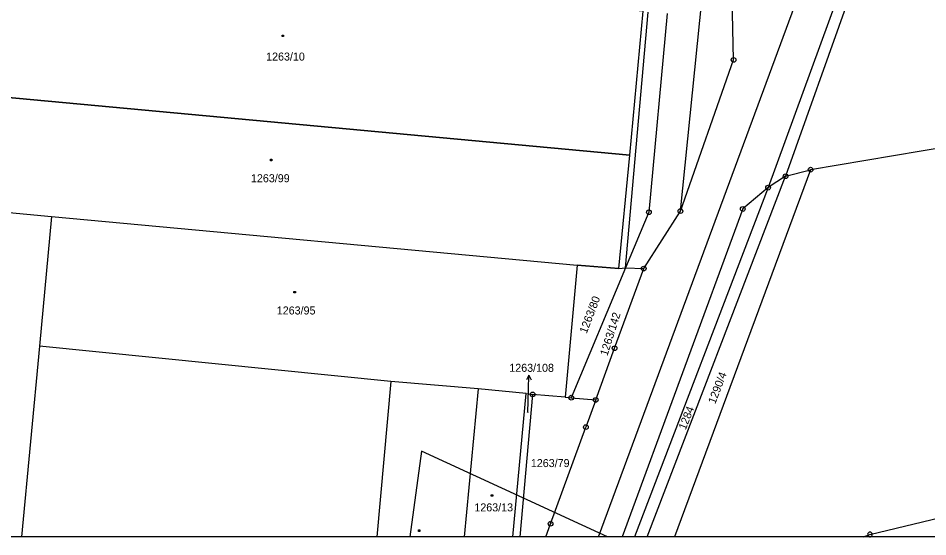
# Model space of a CAD drawing. Extents: x -468021 to -466942, y -1130484 to -1128584.
# Drawn here: x -467501 to -467307.8, y -1130484.4 to -1130374.3 of the extents above; entities that cross this region are included whole.
import ezdxf

# ---------------------------------------------------------------- set-up
doc = ezdxf.new("R2010")
doc.units = 0
for name, color, linetype in [('22-Odběrná místa-šrafy', 7, 'Continuous'), ('Default', 7, 'Continuous'), ('DKM', 7, 'Continuous')]:
    doc.layers.add(name, color=color, linetype=linetype)

msp = doc.modelspace()

# ---------------------------------------------------------------- linework, layer by layer
at = {"layer": '22-Odběrná místa-šrafy'}
for points in [[(-467504.57, -1130390.98), (-467371.12, -1130403.34), (-467368.24, -1130372.8), (-467371.68, -1130372.48), (-467375.66, -1130372.12), (-467378.16, -1130371.89)], [(-467371.12, -1130403.34), (-467504.57, -1130390.98), (-467506.83, -1130415.18), (-467504.4, -1130415.41), (-467493.89, -1130416.38), (-467382.28, -1130426.72), (-467373.43, -1130427.45), (-467371.12, -1130403.34)]]:
    msp.add_lwpolyline(points, dxfattribs=at)
at = {"layer": 'Default'}
msp.add_lwpolyline([(-468020.6, -1128583.91), (-466941.68, -1128583.91), (-466941.68, -1130484.41), (-468020.6, -1130484.41)], close=True, dxfattribs=at)
at = {"layer": 'DKM'}
for p, q in [((-467377.72, -1130484.41), (-467260.66, -1130167.54)), ((-467360.35, -1130415.25), (-467345.02, -1130264.42)), ((-467323.73, -1130360.85), (-467341.73, -1130410.26)), ((-467321.65, -1130361.71), (-467338.03, -1130407.84)), ((-467349.06, -1130383.13), (-467349.37, -1130369.9)), ((-467372, -1130427.28), (-467367.18, -1130372.96)), ((-467371.12, -1130403.34), (-467368.24, -1130372.8)), ((-467363.2, -1130373.31), (-467367.06, -1130415.49)), ((-467444.95, -1130377.87), (-467444.65, -1130377.87)), ((-467444.95, -1130378.17), (-467444.95, -1130377.87)), ((-467444.65, -1130378.17), (-467444.95, -1130378.17)), ((-467444.65, -1130377.87), (-467444.65, -1130378.17)), ((-467360.35, -1130415.25), (-467349.06, -1130383.13)), ((-467210.75, -1130386.12), (-467332.71, -1130406.44)), ((-467371.12, -1130403.34), (-467504.57, -1130390.98)), ((-467447.4, -1130404.23), (-467447.1, -1130404.23)), ((-467447.4, -1130404.53), (-467447.4, -1130404.23)), ((-467447.1, -1130404.23), (-467447.1, -1130404.53)), ((-467373.43, -1130427.45), (-467371.12, -1130403.34)), ((-467447.1, -1130404.53), (-467447.4, -1130404.53)), ((-467367.41, -1130484.41), (-467338.03, -1130407.84)), ((-467332.71, -1130406.44), (-467361.63, -1130484.41)), ((-467338.03, -1130407.84), (-467341.73, -1130410.26)), ((-467338.03, -1130407.84), (-467332.71, -1130406.44)), ((-467341.73, -1130410.26), (-467370.13, -1130484.41)), ((-467341.73, -1130410.26), (-467347.11, -1130414.79)), ((-467504.4, -1130415.41), (-467493.89, -1130416.38)), ((-467347.11, -1130414.79), (-467372.72, -1130484.41)), ((-467367.06, -1130415.49), (-467372, -1130427.28)), ((-467368.15, -1130427.44), (-467360.35, -1130415.25)), ((-467493.89, -1130416.38), (-467496.46, -1130443.91)), ((-467493.89, -1130416.38), (-467382.28, -1130426.72)), ((-467382.28, -1130426.72), (-467384.86, -1130454.74)), ((-467372, -1130427.28), (-467383.54, -1130454.86)), ((-467373.43, -1130427.45), (-467382.28, -1130426.72)), ((-467374.33, -1130444.36), (-467368.15, -1130427.44)), ((-467373.43, -1130427.45), (-467372, -1130427.28)), ((-467372, -1130427.28), (-467368.15, -1130427.44)), ((-467442.43, -1130432.32), (-467442.13, -1130432.32)), ((-467442.43, -1130432.62), (-467442.43, -1130432.32)), ((-467442.13, -1130432.62), (-467442.43, -1130432.62)), ((-467442.13, -1130432.32), (-467442.13, -1130432.62)), ((-467496.46, -1130443.91), (-467500.26, -1130484.41)), ((-467421.87, -1130451.44), (-467496.46, -1130443.91)), ((-467378.34, -1130455.35), (-467374.33, -1130444.36)), ((-467392.55, -1130450.06), (-467393.08, -1130451.05)), ((-467392.63, -1130453.06), (-467392.55, -1130450.06)), ((-467392.55, -1130450.06), (-467392.08, -1130451.07)), ((-467421.87, -1130451.44), (-467424.85, -1130484.41)), ((-467403.29, -1130453.01), (-467421.87, -1130451.44)), ((-467403.29, -1130453.01), (-467406.29, -1130484.41)), ((-467393.11, -1130453.97), (-467403.29, -1130453.01)), ((-467395.97, -1130484.41), (-467393.11, -1130453.97)), ((-467391.75, -1130454.16), (-467394.48, -1130484.41)), ((-467393.11, -1130453.97), (-467391.75, -1130454.16)), ((-467392.76, -1130457.98), (-467392.63, -1130453.06)), ((-467384.86, -1130454.74), (-467391.75, -1130454.16)), ((-467384.86, -1130454.74), (-467383.54, -1130454.86)), ((-467383.54, -1130454.86), (-467378.34, -1130455.35)), ((-467378.34, -1130455.35), (-467380.44, -1130461.11)), ((-467387.92, -1130481.62), (-467380.44, -1130461.11)), ((-467415.36, -1130466.24), (-467417.83, -1130484.41)), ((-467375.84, -1130484.41), (-467415.36, -1130466.24)), ((-467320.1, -1130483.92), (-467265.4, -1130470.62)), ((-467400.53, -1130475.49), (-467400.23, -1130475.49)), ((-467400.53, -1130475.79), (-467400.53, -1130475.49)), ((-467400.23, -1130475.79), (-467400.53, -1130475.79)), ((-467400.23, -1130475.49), (-467400.23, -1130475.79)), ((-467388.94, -1130484.41), (-467387.92, -1130481.62)), ((-467415.98, -1130482.95), (-467415.68, -1130482.95)), ((-467415.98, -1130483.25), (-467415.98, -1130482.95)), ((-467415.68, -1130483.25), (-467415.98, -1130483.25)), ((-467415.68, -1130482.95), (-467415.68, -1130483.25)), ((-467321.48, -1130484.41), (-467320.1, -1130483.92)), ((-467320.21, -1130484.41), (-467319.99, -1130484.41))]:
    msp.add_line(p, q, dxfattribs=at)
for centre, radius in [((-467349.06, -1130383.13), 0.5), ((-467349.06, -1130383.13), 0.01), ((-467332.71, -1130406.44), 0.5), ((-467332.71, -1130406.44), 0.01), ((-467338.03, -1130407.84), 0.5), ((-467338.03, -1130407.84), 0.01), ((-467341.73, -1130410.26), 0.5), ((-467341.73, -1130410.26), 0.01), ((-467367.06, -1130415.49), 0.5), ((-467367.06, -1130415.49), 0.01), ((-467360.35, -1130415.25), 0.5), ((-467360.35, -1130415.25), 0.01), ((-467347.11, -1130414.79), 0.5), ((-467347.11, -1130414.79), 0.01), ((-467368.15, -1130427.44), 0.5), ((-467368.15, -1130427.44), 0.01), ((-467374.33, -1130444.36), 0.5), ((-467374.33, -1130444.36), 0.01), ((-467391.75, -1130454.16), 0.5), ((-467391.75, -1130454.16), 0.01), ((-467383.54, -1130454.86), 0.5), ((-467383.54, -1130454.86), 0.01), ((-467378.34, -1130455.35), 0.5), ((-467378.34, -1130455.35), 0.01), ((-467380.44, -1130461.11), 0.5), ((-467380.44, -1130461.11), 0.01), ((-467387.92, -1130481.62), 0.5), ((-467387.92, -1130481.62), 0.01), ((-467320.1, -1130483.92), 0.01)]:
    msp.add_circle(centre, radius, dxfattribs=at)
msp.add_arc((-467320.1, -1130483.92), 0.5, 282.7795, 257.2205, dxfattribs=at)

# ---------------------------------------------------------------- texts
for s, height, p in [('1263/10', 1.7, (-467448.34, -1130383.27)), ('1263/99', 1.7, (-467451.56, -1130409.11)), ('1263/95', 1.7, (-467446.08, -1130437.19)), ('1263/108', 1.7, (-467396.7, -1130449.37)), ('1263/108', 0.1, (-467393.01, -1130458.12)), ('1263/79', 1.7, (-467392.12, -1130469.6)), ('1263/13', 1.7, (-467404.12, -1130479.01))]:
    msp.add_text(s, height=height, dxfattribs=at).set_placement(p)
for s, rotation, p in [('1263/80', 69.1535, (-467380.28, -1130441.38)), ('1263/142', 72.6788, (-467375.86, -1130446.11)), ('1290/4', 69.2189, (-467352.96, -1130456.31)), ('1284', 68.1986, (-467359.26, -1130461.83))]:
    msp.add_text(s, height=1.7, rotation=rotation, dxfattribs=at).set_placement(p)

doc.saveas('drawing.dxf')
